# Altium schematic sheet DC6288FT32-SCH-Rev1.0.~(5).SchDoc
size A4
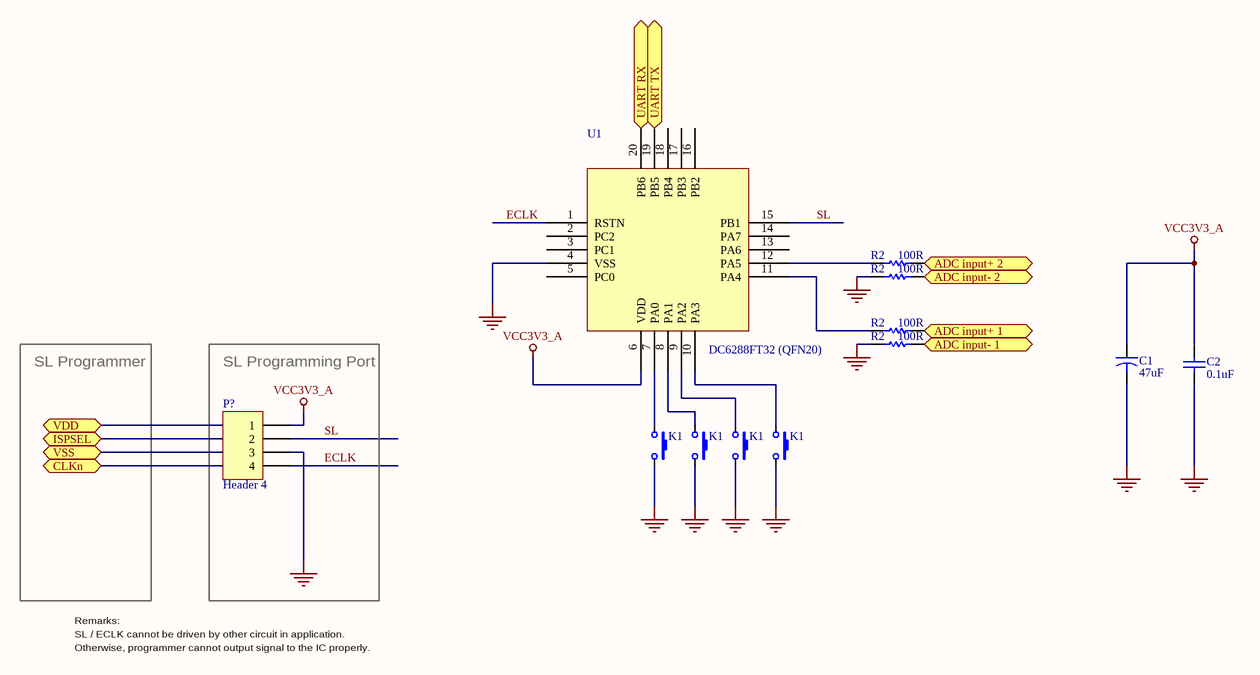
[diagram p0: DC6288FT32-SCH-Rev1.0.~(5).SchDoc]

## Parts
(Parts that share a designator on the sheet are numbered #1, #2 ... from top to bottom, then left to right.)
C1  value 47uF  [CAPR5-4X5]  (hidden comment: Cap2)
C2  value 0.1uF  [RAD-0.3]  (hidden comment: Cap)
K1#1  KEYPAD_SW  [DPST-4]  (value not drawn)
K1#2  KEYPAD_SW  [DPST-4]  (value not drawn)
K1#3  KEYPAD_SW  [DPST-4]  (value not drawn)
K1#4  KEYPAD_SW  [DPST-4]  (value not drawn)
P?  Header 4  [HDR1X4]
R2#1  value 100R  [AXIAL-0.3]  (hidden comment: Res1)
R2#2  value 100R  [AXIAL-0.3]  (hidden comment: Res1)
R2#3  value 100R  [AXIAL-0.3]  (hidden comment: Res1)
R2#4  value 100R  [AXIAL-0.3]  (hidden comment: Res1)
U1  DC6288FT32 (QFN20)  [OTS-28-0.65-01]

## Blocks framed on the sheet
SL Programming Port: P?

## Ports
ADC input+ 1, ADC input+ 2, ADC input- 1, ADC input- 2, CLKn, ISPSEL, UART RX, UART TX, VDD, VSS

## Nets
GND: C1.2 C2.1 K1#1.2 K1#2.2 K1#3.2 K1#4.2 P?.3 R2#2.2 R2#4.2 U1.4(VSS)
VCC3V3_A: C1.1 C2.2 P?.1 U1.6(VDD)
ADC input+ 1: R2#3.1 ; port ADC input+ 1
ADC input+ 2: R2#1.1 ; port ADC input+ 2
ADC input- 1: R2#4.1 ; port ADC input- 1
ADC input- 2: R2#2.1 ; port ADC input- 2
ECLK: P?.4 U1.1(RSTN)
SL: P?.2 U1.15(PB1)
UART RX: U1.20(PB6) ; port UART RX
UART TX: U1.19(PB5) ; port UART TX
NetK1#1_1: K1#1.1 U1.7(PA0)
NetK1#2_1: K1#2.1 U1.8(PA1)
NetK1#3_1: K1#3.1 U1.9(PA2)
NetK1#4_1: K1#4.1 U1.10(PA3)
NetR2#1_2: R2#1.2 U1.12(PA5)
NetR2#3_2: R2#3.2 U1.11(PA4)

Not connected (* = marked no-connect by the designer): U1 2(PC2) 3(PC1) 5(PC0) 13(PA6) 14(PA7) 16(PB2) 17(PB3) 18(PB4)

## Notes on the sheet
- SL Programmer
- Remarks:
- SL / ECLK cannot be driven by other circuit in application.
- Otherwise, programmer cannot output signal to the IC properly.

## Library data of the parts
C1 = Cap2: Capacitor; Manufacturer: Generic Components; Class I: Passive
C2 = Cap: Capacitor; Manufacturer: Generic Components; Class I: Passive
P? = Header 4: Header, 4-Pin
R2#1-R2#4 = Res1: Resistor; Manufacturer: Generic Components; Class I: Passive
